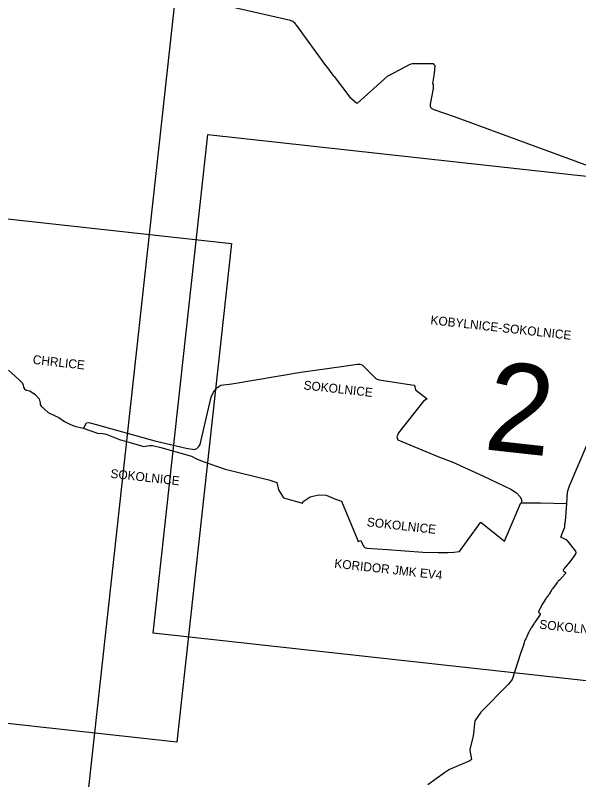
# Model space of a CAD drawing. Extents: x -678204 to -526855, y -1228851 to -1110393.
# Drawn here: x -594386 to -590589, y -1172050 to -1166903 of the extents above; entities that cross this region are included whole.
import ezdxf

# ---------------------------------------------------------------- set-up
doc = ezdxf.new("R2010")
doc.units = 0
for name, color, linetype in [('00_n_cyklo popisy detaily', 7, 'Continuous'), ('00_n_cyklo provereni vedlejsi', 7, 'Continuous'), ('00_n_cyklo prujezdne podminecne rekreacni hlavni', 7, 'Continuous'), ('00_n_cyklo prujezdne rekreacni hlavni', 7, 'Continuous'), ('00_n_cyklo prujezdne rekreacni vedlejsi', 7, 'Continuous'), ('00_n_cyklo realizace rekreacni vedlejsi', 7, 'Continuous'), ('00_n_cyklo studie rekreacni vedlejsi', 7, 'Continuous'), ('00_n_cyklo trasovani rekreacni hlavni', 7, 'Continuous'), ('00_n_cyklo trasovani rekreacni vedlejsi', 7, 'Continuous'), ('_HELP', 7, 'Continuous'), ('_HELP BIG', 7, 'Continuous')]:
    doc.layers.add(name, color=color, linetype=linetype)

msp = doc.modelspace()

# ---------------------------------------------------------------- linework, layer by layer
at = {"layer": '00_n_cyklo provereni vedlejsi'}
msp.add_lwpolyline([(-593926.7, -1169684.5), (-593905.9, -1169647.4), (-593892.1, -1169645.1), (-593881.5, -1169648.2), (-593446.3, -1169768.9), (-593234.8, -1169817.3), (-593177.7, -1169826.1), (-593162.8, -1169819.4), (-593150.4, -1169806.6), (-593141.2, -1169793.4), (-593083.6, -1169551.2), (-593066.2, -1169473.9), (-593051.7, -1169441.9), (-593028.4, -1169411.6), (-593000.1, -1169394.7), (-592926.1, -1169384.7), (-592461.2, -1169305.9), (-592172.9, -1169266.6), (-592081.6, -1169252), (-592062.3, -1169252.8), (-592046.3, -1169259.1), (-592025.3, -1169279.5), (-591955, -1169350.5), (-591935.1, -1169357.8), (-591715.6, -1169391.6), (-591696.5, -1169393.7), (-591694.5, -1169405.5), (-591689, -1169425.5), (-591610.5, -1169486.4), (-591636, -1169501.8), (-591803.8, -1169713.8), (-591814.7, -1169740.9), (-591807.8, -1169760.8), (-591539.7, -1169873.4), (-591438.8, -1169912.3), (-591231.7, -1170006.7), (-591042.2, -1170096.6), (-591007.5, -1170121.7), (-590986, -1170142.8), (-590973.3, -1170168.7), (-590976.4, -1170185.1)], dxfattribs=at)
at = {"layer": '00_n_cyklo prujezdne podminecne rekreacni hlavni'}
for points in [[(-594432.8, -1169293.8), (-594362.1, -1169355.1), (-594337.2, -1169381.1), (-594333.4, -1169393.9), (-594331.1, -1169407.9), (-594325.1, -1169417.5), (-594313.6, -1169426.4), (-594288.5, -1169432.5), (-594252.2, -1169456.9), (-594226, -1169486.7), (-594218.9, -1169512.6), (-594218.8, -1169524.5), (-594212.3, -1169535.7), (-594164.7, -1169577.3), (-594116.8, -1169600.7), (-594093.3, -1169611.7), (-594055.2, -1169637.3), (-594014.4, -1169658.8), (-593985.5, -1169669.8), (-593928.7, -1169684.3), (-593831.5, -1169716.6), (-593796.7, -1169719.6), (-593773.7, -1169723.5), (-593683.1, -1169758.5), (-593536.9, -1169802.5), (-593521.3, -1169805.7), (-593482.3, -1169799.2), (-593461.7, -1169800), (-593405, -1169814), (-593199, -1169870.8), (-593168.6, -1169887.7), (-593153.6, -1169895.3), (-593127.8, -1169905.1), (-592971, -1169958.8), (-592676.8, -1170030.4), (-592624.3, -1170049.2), (-592611.6, -1170098.8), (-592578, -1170152.2)], [(-592578, -1170152.2), (-592449.8, -1170187.8), (-592446.7, -1170177.1), (-592398.9, -1170145.9), (-592342, -1170131.8), (-592290.4, -1170135.2), (-592229.1, -1170162.3), (-592188.8, -1170175.7), (-592077.6, -1170438.5), (-592077.2, -1170445.4), (-592056.9, -1170439.2), (-592040.4, -1170476.8), (-592030.4, -1170486.4), (-592017.2, -1170490.4), (-591877, -1170499.6), (-591639.8, -1170517.3), (-591536.3, -1170521.1), (-591471.8, -1170520.8), (-591430.9, -1170517.9), (-591391.8, -1170513.6)], [(-591391.8, -1170513.6), (-591262.1, -1170333.8), (-591248.3, -1170317.1), (-591089.9, -1170443), (-590979.4, -1170186.1), (-590847.1, -1170186.3), (-590669.8, -1170190.9)]]:
    msp.add_lwpolyline(points, dxfattribs=at)
at = {"layer": '00_n_cyklo prujezdne rekreacni hlavni'}
msp.add_lwpolyline([(-590669.8, -1170190.9), (-590664.4, -1170115.2), (-590660.9, -1170097.9), (-590651.7, -1170071.3), (-590528.5, -1169782.4)], dxfattribs=at)
at = {"layer": '00_n_cyklo prujezdne rekreacni vedlejsi'}
for p, q in [((-590686.1, -1170627), (-590694.8, -1170637.8)), ((-590694.6, -1170640.6), (-590677.5, -1170655.4)), ((-590719.9, -1170705.7), (-590727.4, -1170713.6)), ((-590681.8, -1170664.5), (-590719.9, -1170705.7))]:
    msp.add_line(p, q, dxfattribs=at)
for points in [[(-590686.1, -1170627), (-590647.2, -1170583.1), (-590621.5, -1170549.8), (-590608.7, -1170529.8), (-590606.4, -1170521.5), (-590609.4, -1170510.6), (-590638.1, -1170476.2), (-590648.3, -1170460.7), (-590664.5, -1170441.8), (-590674.4, -1170434.2), (-590711, -1170416.9), (-590684.1, -1170347.4), (-590682.2, -1170331.2), (-590678.2, -1170309.6), (-590669.8, -1170190.8)], [(-590677.3, -1170659.7), (-590681.8, -1170664.5)], [(-590983, -1171206.7), (-591037.3, -1171375.9), (-591063.3, -1171407), (-591250.1, -1171594.7), (-591289.3, -1171653.6), (-591300.6, -1171756.3), (-591322.7, -1171844.3), (-591323.7, -1171854.2), (-591315.2, -1171900.3), (-591312.9, -1171914.1), (-591322.3, -1171923.4), (-591445.5, -1171973.6), (-591459.2, -1171980.9), (-591494.9, -1172003.6), (-591606.2, -1172083.9)]]:
    msp.add_lwpolyline(points, dxfattribs=at)
for centre, radius, start, end in [((-590693.3, -1170639.1), 2, 141.0249, 229.0067), ((-590679.5, -1170657.7), 3, 316.8026, 49.0067)]:
    msp.add_arc(centre, radius, start, end, dxfattribs=at)
at = {"layer": '00_n_cyklo realizace rekreacni vedlejsi'}
for p, q in [((-590727.4, -1170713.6), (-590727.7, -1170713.9)), ((-590734.6, -1170722), (-590767.1, -1170764.6)), ((-590795.7, -1170810.5), (-590802.9, -1170820)), ((-590773.7, -1170774.5), (-590789.4, -1170801.1)), ((-590808.7, -1170828.3), (-590833.6, -1170866.3)), ((-590841.3, -1170879.6), (-590860.6, -1170916.9)), ((-590849, -1170936.9), (-590887.5, -1170993.7)), ((-590858.6, -1170924.1), (-590850.6, -1170929.2)), ((-590891.7, -1171000.2), (-590907.6, -1171025.2)), ((-590929.1, -1171063.4), (-590940.2, -1171088.4)), ((-590912.1, -1171032.6), (-590921.4, -1171048.4)), ((-590955.5, -1171114.8), (-590956.1, -1171128)), ((-590953.7, -1171110.3), (-590955.5, -1171114.8)), ((-590945.5, -1171101.2), (-590953.7, -1171110.3)), ((-590941.9, -1171092.9), (-590943.3, -1171096.9)), ((-590958.6, -1171138.4), (-590983, -1171206.7))]:
    msp.add_line(p, q, dxfattribs=at)
for centre, radius, start, end in [((-590687.6, -1170825.3), 100, 142.6663, 149.4648), ((-590655.1, -1170782.7), 100, 136.5766, 142.6663), ((-590875.5, -1170750.3), 100, 322.9594, 329.4648), ((-590708, -1170948.4), 150, 146.8194, 152.6979), ((-590683.2, -1170910.3), 150, 142.9594, 146.8194), ((-590855.7, -1170919.4), 5.5, 152.6979, 237.6868), ((-590853.5, -1170933.8), 5.5, 325.845, 57.6868), ((-590680.6, -1171134), 250, 145.845, 147.6286), ((-590792, -1171124.3), 150, 149.5968, 156.047), ((-590696.5, -1171159.1), 250, 147.6286, 149.5968), ((-590957.5, -1171092.1), 15, 322.8178, 341.4779), ((-590894.5, -1171108.7), 50, 156.047, 161.4779), ((-591005.7, -1171121.6), 50, 340.389, 352.614)]:
    msp.add_arc(centre, radius, start, end, dxfattribs=at)
at = {"layer": '00_n_cyklo studie rekreacni vedlejsi'}
for points in [[(-592237.9, -1167314.7), (-592286.2, -1167247.9), (-592294.6, -1167240.5), (-592488.4, -1166972.1), (-592500.1, -1166958.2), (-592514.9, -1166946), (-592531.9, -1166938.4), (-593895.3, -1166627.3), (-593905.3, -1166619.8), (-594008.1, -1166597), (-594053.4, -1166583.7), (-594110.3, -1166563.2)], [(-591565.6, -1167231.2), (-591692.6, -1167229.8), (-591711, -1167230.5), (-591728.1, -1167234.9), (-591756.9, -1167250.9), (-591879.9, -1167315.1)], [(-591571.9, -1167363.2), (-591562, -1167294.6), (-591556.7, -1167244.5), (-591565.6, -1167235.3), (-591565.6, -1167231.2)], [(-592237.9, -1167314.7), (-592132.6, -1167455.6), (-592085.9, -1167492.3), (-592079.3, -1167494.2), (-591879.9, -1167315.1)], [(-589989.7, -1168225.7), (-590044.3, -1168200.4), (-590090.5, -1168172), (-590439.8, -1167957.9), (-590503.7, -1167925.6), (-591427.5, -1167586.2), (-591562.6, -1167539.3), (-591577.2, -1167532.2), (-591587.8, -1167521.2), (-591588.4, -1167501.3), (-591568.7, -1167396.5), (-591567.7, -1167369.3), (-591571.9, -1167363.2)]]:
    msp.add_lwpolyline(points, dxfattribs=at)
at = {"layer": '00_n_cyklo trasovani rekreacni hlavni'}
for points in [[(-594432.8, -1169293.8), (-594362.1, -1169355.1), (-594337.2, -1169381.1), (-594333.4, -1169393.9), (-594331.1, -1169407.9), (-594325.1, -1169417.5), (-594313.6, -1169426.4), (-594288.5, -1169432.5), (-594252.2, -1169456.9), (-594226, -1169486.7), (-594218.9, -1169512.6), (-594218.8, -1169524.5), (-594212.3, -1169535.7), (-594164.7, -1169577.3), (-594116.8, -1169600.7), (-594093.3, -1169611.7), (-594055.2, -1169637.3), (-594014.4, -1169658.8), (-593985.5, -1169669.8), (-593928.7, -1169684.3), (-593831.5, -1169716.6), (-593796.7, -1169719.6), (-593773.7, -1169723.5), (-593683.1, -1169758.5), (-593536.9, -1169802.5), (-593521.3, -1169805.7), (-593482.3, -1169799.2), (-593461.7, -1169800), (-593405, -1169814), (-593199, -1169870.8), (-593168.6, -1169887.7), (-593153.6, -1169895.3), (-593127.8, -1169905.1), (-592971, -1169958.8), (-592676.8, -1170030.4), (-592624.3, -1170049.2), (-592611.6, -1170098.8), (-592578, -1170152.2)], [(-590669.8, -1170190.9), (-590664.4, -1170115.2), (-590660.9, -1170097.9), (-590651.7, -1170071.3), (-590528.5, -1169782.4)], [(-592578, -1170152.2), (-592449.8, -1170187.8), (-592446.7, -1170177.1), (-592398.9, -1170145.9), (-592342, -1170131.8), (-592290.4, -1170135.2), (-592229.1, -1170162.3), (-592188.8, -1170175.7), (-592077.6, -1170438.5), (-592077.2, -1170445.4), (-592056.9, -1170439.2), (-592040.4, -1170476.8), (-592030.4, -1170486.4), (-592017.2, -1170490.4), (-591877, -1170499.6), (-591639.8, -1170517.3), (-591536.3, -1170521.1), (-591471.8, -1170520.8), (-591430.9, -1170517.9), (-591391.8, -1170513.6)], [(-591391.8, -1170513.6), (-591262.1, -1170333.8), (-591248.3, -1170317.1), (-591089.9, -1170443), (-590979.4, -1170186.1), (-590847.1, -1170186.3), (-590669.8, -1170190.9)]]:
    msp.add_lwpolyline(points, dxfattribs=at)
at = {"layer": '00_n_cyklo trasovani rekreacni vedlejsi'}
for p, q in [((-590686.1, -1170627), (-590694.8, -1170637.8)), ((-590694.6, -1170640.6), (-590677.5, -1170655.4)), ((-590727.4, -1170713.6), (-590727.7, -1170713.9)), ((-590719.9, -1170705.7), (-590727.4, -1170713.6)), ((-590681.8, -1170664.5), (-590719.9, -1170705.7)), ((-590734.6, -1170722), (-590767.1, -1170764.6)), ((-590795.7, -1170810.5), (-590802.9, -1170820)), ((-590773.7, -1170774.5), (-590789.4, -1170801.1)), ((-590808.7, -1170828.3), (-590833.6, -1170866.3)), ((-590841.3, -1170879.6), (-590860.6, -1170916.9)), ((-590849, -1170936.9), (-590887.5, -1170993.7)), ((-590858.6, -1170924.1), (-590850.6, -1170929.2)), ((-590891.7, -1171000.2), (-590907.6, -1171025.2)), ((-590929.1, -1171063.4), (-590940.2, -1171088.4)), ((-590912.1, -1171032.6), (-590921.4, -1171048.4)), ((-590955.5, -1171114.8), (-590956.1, -1171128)), ((-590953.7, -1171110.3), (-590955.5, -1171114.8)), ((-590945.5, -1171101.2), (-590953.7, -1171110.3)), ((-590941.9, -1171092.9), (-590943.3, -1171096.9)), ((-590958.6, -1171138.4), (-590983, -1171206.7))]:
    msp.add_line(p, q, dxfattribs=at)
for points in [[(-592237.9, -1167314.7), (-592286.2, -1167247.9), (-592294.6, -1167240.5), (-592488.4, -1166972.1), (-592500.1, -1166958.2), (-592514.9, -1166946), (-592531.9, -1166938.4), (-593895.3, -1166627.3), (-593905.3, -1166619.8), (-594008.1, -1166597), (-594053.4, -1166583.7), (-594110.3, -1166563.2)], [(-591565.6, -1167231.2), (-591692.6, -1167229.8), (-591711, -1167230.5), (-591728.1, -1167234.9), (-591756.9, -1167250.9), (-591879.9, -1167315.1)], [(-591571.9, -1167363.2), (-591562, -1167294.6), (-591556.7, -1167244.5), (-591565.6, -1167235.3), (-591565.6, -1167231.2)], [(-592237.9, -1167314.7), (-592132.6, -1167455.6), (-592085.9, -1167492.3), (-592079.3, -1167494.2), (-591879.9, -1167315.1)], [(-589989.7, -1168225.7), (-590044.3, -1168200.4), (-590090.5, -1168172), (-590439.8, -1167957.9), (-590503.7, -1167925.6), (-591427.5, -1167586.2), (-591562.6, -1167539.3), (-591577.2, -1167532.2), (-591587.8, -1167521.2), (-591588.4, -1167501.3), (-591568.7, -1167396.5), (-591567.7, -1167369.3), (-591571.9, -1167363.2)], [(-593926.7, -1169684.5), (-593905.9, -1169647.4), (-593892.1, -1169645.1), (-593881.5, -1169648.2), (-593446.3, -1169768.9), (-593234.8, -1169817.3), (-593177.7, -1169826.1), (-593162.8, -1169819.4), (-593150.4, -1169806.6), (-593141.2, -1169793.4), (-593083.6, -1169551.2), (-593066.2, -1169473.9), (-593051.7, -1169441.9), (-593028.4, -1169411.6), (-593000.1, -1169394.7), (-592926.1, -1169384.7), (-592461.2, -1169305.9), (-592172.9, -1169266.6), (-592081.6, -1169252), (-592062.3, -1169252.8), (-592046.3, -1169259.1), (-592025.3, -1169279.5), (-591955, -1169350.5), (-591935.1, -1169357.8), (-591715.6, -1169391.6), (-591696.5, -1169393.7), (-591694.5, -1169405.5), (-591689, -1169425.5), (-591610.5, -1169486.4), (-591636, -1169501.8), (-591803.8, -1169713.8), (-591814.7, -1169740.9), (-591807.8, -1169760.8), (-591539.7, -1169873.4), (-591438.8, -1169912.3), (-591231.7, -1170006.7), (-591042.2, -1170096.6), (-591007.5, -1170121.7), (-590986, -1170142.8), (-590973.3, -1170168.7), (-590976.4, -1170185.1)], [(-590686.1, -1170627), (-590647.2, -1170583.1), (-590621.5, -1170549.8), (-590608.7, -1170529.8), (-590606.4, -1170521.5), (-590609.4, -1170510.6), (-590638.1, -1170476.2), (-590648.3, -1170460.7), (-590664.5, -1170441.8), (-590674.4, -1170434.2), (-590711, -1170416.9), (-590684.1, -1170347.4), (-590682.2, -1170331.2), (-590678.2, -1170309.6), (-590669.8, -1170190.8)], [(-590677.3, -1170659.7), (-590681.8, -1170664.5)], [(-590983, -1171206.7), (-591037.3, -1171375.9), (-591063.3, -1171407), (-591250.1, -1171594.7), (-591289.3, -1171653.6), (-591300.6, -1171756.3), (-591322.7, -1171844.3), (-591323.7, -1171854.2), (-591315.2, -1171900.3), (-591312.9, -1171914.1), (-591322.3, -1171923.4), (-591445.5, -1171973.6), (-591459.2, -1171980.9), (-591494.9, -1172003.6), (-591606.2, -1172083.9)]]:
    msp.add_lwpolyline(points, dxfattribs=at)
for centre, radius, start, end in [((-590693.3, -1170639.1), 2, 141.0249, 229.0067), ((-590679.5, -1170657.7), 3, 316.8026, 49.0067), ((-590687.6, -1170825.3), 100, 142.6663, 149.4648), ((-590655.1, -1170782.7), 100, 136.5766, 142.6663), ((-590875.5, -1170750.3), 100, 322.9594, 329.4648), ((-590708, -1170948.4), 150, 146.8194, 152.6979), ((-590683.2, -1170910.3), 150, 142.9594, 146.8194), ((-590855.7, -1170919.4), 5.5, 152.6979, 237.6868), ((-590853.5, -1170933.8), 5.5, 325.845, 57.6868), ((-590680.6, -1171134), 250, 145.845, 147.6286), ((-590792, -1171124.3), 150, 149.5968, 156.047), ((-590696.5, -1171159.1), 250, 147.6286, 149.5968), ((-590957.5, -1171092.1), 15, 322.8178, 341.4779), ((-590894.5, -1171108.7), 50, 156.047, 161.4779), ((-591005.7, -1171121.6), 50, 340.389, 352.614)]:
    msp.add_arc(centre, radius, start, end, dxfattribs=at)
at = {"layer": '_HELP'}
for points in [[(-593089.1, -1167705.7), (-588374.6, -1168223.4), (-588743.3, -1171580.9), (-593457.8, -1171063.2)], [(-597643.4, -1167921.6), (-592928.8, -1168439.3), (-593297.5, -1171796.8), (-598012.1, -1171279.1)]]:
    msp.add_lwpolyline(points, close=True, dxfattribs=at)
at = {"layer": '_HELP BIG'}
msp.add_lwpolyline([(-616541.9, -1192690.5), (-613435.7, -1164403.2), (-593290.7, -1166615.3), (-596396.9, -1194902.6)], close=True, dxfattribs=at)

# ---------------------------------------------------------------- texts
at = {"layer": '00_n_cyklo popisy detaily'}
for s, p in [('KOBYLNICE-SOKOLNICE', (-591590.7, -1168983.4)), ('KOBYLNICE-SOKOLNICE', (-591590.7, -1168983.4)), ('KOBYLNICE-SOKOLNICE', (-591590.7, -1168983.4)), ('CHRLICE', (-594270.9, -1169249.9)), ('SOKOLNICE', (-592445.9, -1169422)), ('SOKOLNICE', (-593747.2, -1170017.1)), ('SOKOLNICE', (-592019.4, -1170343.5)), ('KORIDOR JMK EV4', (-592238.5, -1170622.5)), ('SOKOLNICE-TELNICE', (-590857.2, -1171032.2)), ('SOKOLNICE-TELNICE', (-590857.2, -1171032.2)), ('SOKOLNICE-TELNICE', (-590857.2, -1171032.2))]:
    msp.add_text(s, height=60, rotation=353.6836, dxfattribs=at).set_placement(p)
at = {"layer": '_HELP'}
msp.add_text('2', height=600, rotation=353.6836, dxfattribs=at).set_placement((-591237.5, -1169824.3))

doc.saveas('drawing.dxf')
